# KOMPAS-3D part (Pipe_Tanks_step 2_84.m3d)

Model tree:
1. X Axis
2. Y Axis
3. Z Axis  (labels: Bend 90 Dn 50; Pipe Dn 50)
     Òîëùèíà ñòåíêè 1 = 1

Referenced files in C:\Documents and Settings\kashirsky\Мои документы\Camtasia Studio\Pipelines3D\Tanks\: Tanks_step 4.a3d
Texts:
  Pipe Dn 50
  Steel ASTM A295
  Three Point Plane
  Plane at Angle
  Line and Point Plane
  Axis through Two Vertices
  Axis of Feature
  Axis of Conical Surface
  Axis through Edge
  Trim by Surface
  Trim by Sketch
  Feature with No History
  Intersection Axis of Two Planes
  Two Line Plane
  Line and Face Plane
  Bend by line
  Hole in sheet body
  Cut in sheet body
  Point in CM
  Linear Dimension from Line to Point
  Surface Finish Symbol
  Geometric Tolerance Symbol
  Leader #1
  Leader #2
  Leader #3
  Shape Deviations and Datum
  Node point number
  Mark of coordination axis
  Node point designation
  Mark/Reference designation with leader
  Mark/reference designation on line
  Mark/Reference designation without leader
  Bend 90 Dn 50
  Plane of section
